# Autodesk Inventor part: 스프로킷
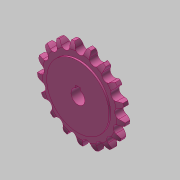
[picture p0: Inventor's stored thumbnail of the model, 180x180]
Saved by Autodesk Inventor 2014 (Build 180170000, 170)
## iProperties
Created: 2019-06
Part Number: 스프로킷
Material: 알루미늄 6061
Document SubType Name: Modeling
Designer: mduedu
Density: 1 g/cm^3
Appearance: 분홍색
Author: mduedu
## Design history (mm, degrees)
sketch "스케치1"
  geometry: L1 (0, 0)-(-3.6, 0); L2 (-3.6, 0)-(-3.6, 32.203); L3 (-2, 38)-(0, 38); L4 (0, 38)-(0, 0); L5 (0, 0)-(3.6, 0); L6 (3.6, 0)-(3.6, 32.203); L7 (2, 38)-(0, 38); A1 r 13.5 centre (9.887, 31.6) between (-2, 38) and (-3.6, 32.203); A2 r 13.5 centre (-9.887, 31.6) between (3.6, 32.203) and (2, 38)
  constraints: 14 end point, 4 point on circle, 4 symmetric about line, 2 centre point, 2 perpendicular, 1 horizontal, 1 parallel, 1 other
  dimensions: "d0" = 76 diameter of L3 L1; "d2" = 7.2 distance between parallel lines of L6 L2; "d3" = 1.6 distance from line of L3.start L2; "d4" = 6.4 distance from line of A2.centre L3; "d5" = 13.5 radius of A1
revolve "회전1" sketch "스케치1" stored, may be unused: angle "d6" = 90 deg
sketch "스케치2"
  geometry: L1 (34.56, 0)-(-34.56, 0); A1 r 34.56 centre (0, 0) between (34.56, 0) and (30.537, -16.182); A2 r 3.975 centre (34.56, 0) between (33.601, 3.858) and (33.601, -3.858); A3 r 12.7 centre (30.537, -16.182) between (37.583, -5.616) and (33.601, -3.858); A4 r 12.7 centre (30.537, 16.182) between (33.601, 3.858) and (37.583, 5.616); A5 r 38 centre (0, 0) between (37.583, -5.616) and (37.583, 5.616); 2 further points
  constraints: 11 point on circle, 5 centre point, 2 coincident, 2 end point, 2 symmetric about line, 1 horizontal, 1 horizontal alignment, 1 tangent, 3 other
  dimensions: "d7" = 69.12 diameter of A1; "d8" = 7.95 diameter of A2; "d9" = 12.7 radius of A3
extrude "돌출1" cut sketch "스케치2" stored distance "d10" = 10; taper "d11" = 0 deg
sketch "스케치3"
  geometry: C1 r 27 at (0, 0); 1 further point
  constraints: 1 centre point, 1 coincident
  dimensions: "d15" = 54 diameter of C1
extrude "돌출2" join sketch "스케치3" stored distance "d16" = 10; taper "d17" = 0 deg
sketch "스케치4"
  geometry: C1 r 11 at (0, 0); 1 further point
  constraints: 1 centre point, 1 coincident
  dimensions: "d18" = 22 diameter of C1
extrude "돌출3" join sketch "스케치4" distance "d19" = 11; taper "d20" = 0 deg
fillet "모깎기1" dims "d21" = 3
sketch "스케치5"
  geometry: L1 (-2, 5.657)-(2, 5.657); L2 (2, 5.657)-(2, 7.8); L3 (2, 7.8)-(-2, 7.8); L4 (-2, 7.8)-(-2, 5.657); A1 r 6 centre (0, 0) between (-2, 5.657) and (2, 5.657); 1 further point
  constraints: 8 end point, 2 parallel, 2 point on circle, 1 centre point, 1 coincident, 1 horizontal, 1 perpendicular
  dimensions: "d24" = 13.8 dimension on A1 L3; "d26" = 4 distance between parallel lines of L2 L4; "d27" = 12 diameter of A1
extrude "돌출4" cut sketch "스케치5" stored distance "d28" = 11; taper "d29" = 0 deg
chamfer "모따기1" distance "d30" = 0.5; stored, may be unused: second distance "d31" = 2, angle "d32" = 45 deg
node "솔리드1"
pattern_circular "원형 패턴1" dims angle "d13" = 360 deg
